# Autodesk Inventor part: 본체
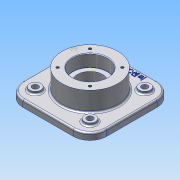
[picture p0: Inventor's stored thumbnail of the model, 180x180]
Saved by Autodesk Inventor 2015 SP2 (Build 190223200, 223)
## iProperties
Created: 2015-07
Part Number: 본체
Material: 알루미늄 6061
Document SubType Name: Modeling
Designer: AMC
Density: 2.7 g/cm^3
Appearance: 알루미늄 - 평지
Mass: 1459.27 g
Surface Area: 800.934 cm^2
Volume: 540.471 cm^3
Author: AMC
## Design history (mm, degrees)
sketch "스케치1"
  geometry: L1 (-75, 75)-(75, 75); L2 (75, 75)-(75, -75); L3 (75, -75)-(-75, -75); L4 (-75, -75)-(-75, 75); L5 (-75, 75)-(75, -75); L6 (75, 75)-(-75, -75); 1 further point
  constraints: 12 end point, 2 midpoint, 2 parallel, 1 horizontal, 1 perpendicular
  dimensions: "d0" = 150 distance of L2.end L3.end; "d1" = 150 distance of L1.end L2.end
extrude "돌출1" new body sketch "스케치1" distance "d2" = 12; taper "d3" = 0 deg
sketch "스케치2"
  geometry: C1 r 50 at (0, 0); 1 further point
  constraints: 1 centre point, 1 coincident
  dimensions: "d4" = 100 diameter of C1
extrude "돌출2" join sketch "스케치2" distance "d5" = 47; taper "d7" = 0 deg; dims "d6" = 23, "d8" = 0
hole "구멍1" diameter "d11" = 45; stored, may be unused: countersink angle "d15" = 90 deg, drill point angle "d17" = 118 deg; dims "d9" = 10, "d10" = 10, "d12" = 6, "d13" = 62, "d14" = 22, "d16" = 8
hole "구멍2" diameter "d20" = 45; stored, may be unused: countersink angle "d24" = 90 deg, drill point angle "d26" = 118 deg; dims "d18" = 10, "d19" = 10, "d21" = 6, "d22" = 62, "d23" = 22, "d25" = 8
sketch "스케치3"
  geometry: L1 (0, 0)-(41, 0); L2 (0, 0)-(28.991, 28.991); A1 r 41 centre (0, 0) between (41, 0) and (28.991, 28.991); 2 further points
  constraints: 4 end point, 2 coincident, 2 point on circle, 1 centre point, 1 horizontal
  dimensions: "d27" = 82 diameter of A1; "d28" = 45 deg angle of L1 L2
hole "구멍3" sketch "스케치3" at (28.991, 28.991) diameter "d29" = 4.917; stored, may be unused: countersink angle "d33" = 90 deg, drill point angle "d35" = 118 deg; dims "d30" = 10, "d31" = 62, "d32" = 22, "d34" = 13
sketch "스케치4"
  geometry: L1 (0, 0)-(0, 41); L2 (0, 0)-(-28.991, 28.991); A1 r 41 centre (0, 0) between (0, 41) and (-28.991, 28.991); 2 further points
  constraints: 4 end point, 2 coincident, 2 point on circle, 1 centre point, 1 vertical
  dimensions: "d39" = 82 diameter of A1; "d40" = 45 deg angle of L1 L2
hole "구멍4" sketch "스케치4" at (-28.991, 28.991) diameter "d41" = 4.917; stored, may be unused: countersink angle "d45" = 90 deg, drill point angle "d47" = 118 deg; dims "d42" = 10, "d43" = 62, "d44" = 22, "d46" = 13
sketch "스케치5"
  geometry: L1 (-75, -75)-(-75, 75) reference; L2 (-75, 75)-(75, 75) reference; C1 r 10 at (-49, 49); C2 r 10 at (49, 49); C3 r 10 at (49, -49); C4 r 10 at (-49, -49); 5 further points
  constraints: 4 centre point, 4 coincident, 2 horizontal alignment, 2 vertical alignment
  dimensions: "d51" = 26 distance from line of L1 point (-49, 49); "d52" = 26 distance from line of L2 point (-49, 49); "d53" = 98 distance of point (49, 49) point (-49, 49); "d54" = 98 distance of point (-49, -49) point (-49, 49); "d55" = 20 diameter of C1; "d56" = 20 diameter of C2; "d57" = 20 diameter of C3; "d58" = 20 diameter of C4
extrude "돌출3" join sketch "스케치5" distance "d59" = 5; taper "d60" = 0 deg
hole "구멍5" diameter "d63" = 11; stored, may be unused: countersink angle "d67" = 90 deg, drill point angle "d69" = 118 deg; dims "d61" = 10, "d62" = 10, "d64" = 11, "d65" = 62, "d66" = 22, "d68" = 13
hole "구멍6" diameter "d72" = 11; stored, may be unused: countersink angle "d76" = 90 deg, drill point angle "d78" = 118 deg; dims "d70" = 10, "d71" = 10, "d73" = 11, "d74" = 62, "d75" = 22, "d77" = 13
hole "구멍7" diameter "d81" = 11; stored, may be unused: countersink angle "d85" = 90 deg, drill point angle "d87" = 118 deg; dims "d79" = 10, "d80" = 10, "d82" = 11, "d83" = 62, "d84" = 22, "d86" = 13
hole "구멍8" diameter "d90" = 11; stored, may be unused: countersink angle "d94" = 90 deg, drill point angle "d96" = 118 deg; dims "d88" = 10, "d89" = 10, "d91" = 11, "d92" = 62, "d93" = 22, "d95" = 13
fillet "모깎기1" dims "d97" = 30
fillet "모깎기2" dims "d98" = 3
fillet "모깎기3" dims "d99" = 3
fillet "모깎기4" dims "d100" = 0.3
chamfer "모따기1" distance "d101" = 1; stored, may be unused: second distance "d102" = 2, angle "d103" = 45 deg
sketch "스케치6"
  geometry: 2 further points
  constraints: 1 vertical alignment, 1 other
  dimensions: "d104" = 65 distance of point (0, 0) point (0, 65)
feature "엠보싱1" sketch "스케치6" dims "d0" = 150, "d1" = 150, "d105" = 1, "d106" = 0
node "솔리드1"
pattern_circular "원형 패턴1" dims angle "d37" = 360 deg
pattern_circular "원형 패턴2" dims angle "d49" = 360 deg
